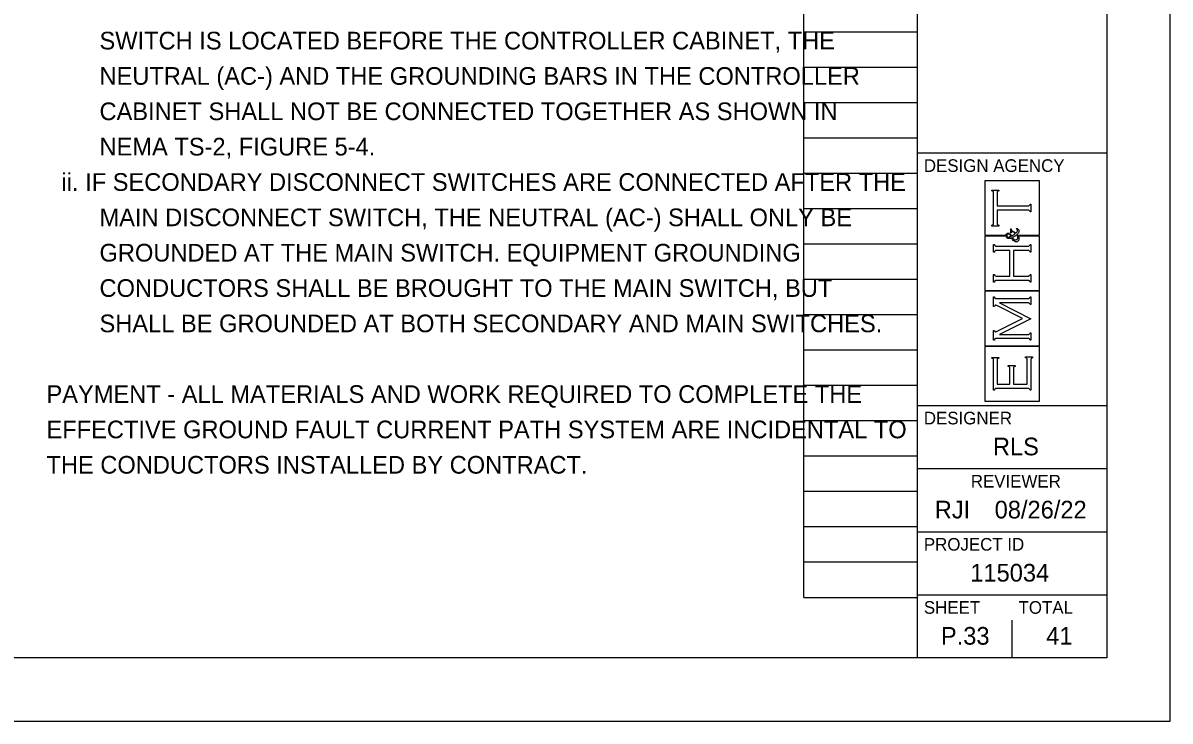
# Model space of a CAD drawing. Extents: x 0 to 34, y -30 to 22.
# Drawn here: x 24.91 to 34, y 0 to 5.53 of the extents above; entities that cross this region are included whole.
import ezdxf

# ---------------------------------------------------------------- set-up
doc = ezdxf.new("R2010")
doc.units = 0
for name, color, linetype in [('SH_Border', 7, 'Continuous'), ('SH_Cut_Line', 7, 'Continuous'), ('SH_Data', 7, 'Continuous'), ('SH_Text', 7, 'Continuous')]:
    doc.layers.add(name, color=color, linetype=linetype)

msp = doc.modelspace()

# ---------------------------------------------------------------- linework, layer by layer
at = {"layer": 'SH_Border'}
for p, q in [((32, 0.5), (32, 21.5)), ((32, 4.5), (33.5, 4.5)), ((32, 2.5), (33.5, 2.5)), ((32, 2), (33.5, 2)), ((32, 1.5), (33.5, 1.5)), ((32, 1), (33.5, 1))]:
    msp.add_line(p, q, dxfattribs=at)
msp.add_lwpolyline([(1.5, 21.5), (33.5, 21.5), (33.5, 0.5), (1.5, 0.5)], close=True, dxfattribs=at)
at = {"layer": 'SH_Cut_Line'}
msp.add_lwpolyline([(0, 0), (34, 0), (34, 22), (0, 22)], close=True, dxfattribs=at)
at = {"layer": 'SH_Data'}
for p, q in [((31.1, 0.98), (31.1, 21.14)), ((32, 0.98), (32, 21.14)), ((31.1, 5.46), (32, 5.46)), ((31.1, 5.18), (32, 5.18)), ((31.1, 4.9), (32, 4.9)), ((31.1, 4.62), (32, 4.62)), ((31.1, 4.34), (32, 4.34)), ((32.966, 4.2797), (32.5341, 4.2797)), ((32.5341, 4.2797), (32.5341, 3.848)), ((32.966, 3.848), (32.966, 4.2797)), ((32.5883, 4.1994), (32.5883, 4.2063)), ((32.5883, 4.2063), (32.6445, 4.2063)), ((32.5938, 4.1981), (32.5883, 4.1994)), ((32.5975, 4.1962), (32.5938, 4.1981)), ((32.5994, 4.1936), (32.5975, 4.1962)), ((32.6012, 4.1911), (32.5994, 4.1936)), ((32.6021, 4.1868), (32.6012, 4.1911)), ((32.6021, 4.1808), (32.6021, 4.1868)), ((32.6021, 3.9469), (32.6021, 4.1808)), ((32.6316, 4.1911), (32.6306, 4.1868)), ((32.6306, 4.1868), (32.6306, 4.1808)), ((32.6306, 4.1808), (32.6306, 4.0808)), ((32.6334, 4.1936), (32.6316, 4.1911)), ((32.6352, 4.1962), (32.6334, 4.1936)), ((32.6389, 4.1981), (32.6352, 4.1962)), ((32.6445, 4.1994), (32.6389, 4.1981)), ((32.6445, 4.2063), (32.6445, 4.1994)), ((32.8875, 4.0855), (32.8895, 4.0892)), ((32.8895, 4.0892), (32.8909, 4.0946)), ((32.8909, 4.0946), (32.8978, 4.0946)), ((32.8978, 4.0946), (32.8978, 4.033)), ((31.1, 4.06), (32, 4.06)), ((32.6306, 4.0808), (32.8723, 4.0808)), ((32.8723, 4.0469), (32.6306, 4.0469)), ((32.6306, 4.0469), (32.6306, 3.9469)), ((32.8723, 4.0808), (32.8782, 4.0808)), ((32.8784, 4.0469), (32.8723, 4.0469)), ((32.8782, 4.0808), (32.8824, 4.0817)), ((32.8826, 4.046), (32.8784, 4.0469)), ((32.8824, 4.0817), (32.885, 4.0836)), ((32.8851, 4.0441), (32.8826, 4.046)), ((32.885, 4.0836), (32.8875, 4.0855)), ((32.8875, 4.0422), (32.8851, 4.0441)), ((32.8895, 4.0385), (32.8875, 4.0422)), ((32.8909, 4.033), (32.8895, 4.0385)), ((32.8978, 4.033), (32.8909, 4.033)), ((32.5883, 3.9283), (32.5938, 3.9296)), ((32.5883, 3.9214), (32.5883, 3.9283)), ((32.6445, 3.9214), (32.5883, 3.9214)), ((32.5938, 3.9296), (32.5975, 3.9315)), ((32.5975, 3.9315), (32.5994, 3.934)), ((32.5994, 3.934), (32.6012, 3.9366)), ((32.6012, 3.9366), (32.6021, 3.9409)), ((32.6021, 3.9409), (32.6021, 3.9469)), ((32.6306, 3.9469), (32.6306, 3.9409)), ((32.6306, 3.9409), (32.6315, 3.9366)), ((32.6315, 3.9366), (32.6334, 3.934)), ((32.6334, 3.934), (32.6352, 3.9315)), ((32.6352, 3.9315), (32.6389, 3.9296)), ((32.6389, 3.9296), (32.6445, 3.9283)), ((32.6445, 3.9283), (32.6445, 3.9214)), ((32.5341, 3.848), (32.6932, 3.848)), ((32.6927, 3.8421), (32.5341, 3.8421)), ((32.5341, 3.8421), (32.5341, 3.4103)), ((32.6932, 3.848), (32.6927, 3.8421)), ((32.7011, 3.8522), (32.7028, 3.8569)), ((32.7011, 3.8465), (32.7011, 3.8522)), ((32.7011, 3.8405), (32.7011, 3.8465)), ((32.7027, 3.8351), (32.7011, 3.8405)), ((32.7061, 3.8304), (32.7027, 3.8351)), ((32.7028, 3.8569), (32.7061, 3.8605)), ((32.7061, 3.8605), (32.7095, 3.8641)), ((32.7104, 3.8243), (32.7061, 3.8304)), ((32.7074, 3.8521), (32.7063, 3.8494)), ((32.7063, 3.8494), (32.7063, 3.8463)), ((32.7063, 3.8463), (32.7063, 3.8421)), ((32.7063, 3.8421), (32.7077, 3.8389)), ((32.7097, 3.8543), (32.7074, 3.8521)), ((32.7077, 3.8389), (32.7106, 3.8368)), ((32.7095, 3.8641), (32.7137, 3.8659)), ((32.7119, 3.8564), (32.7097, 3.8543)), ((32.7167, 3.8213), (32.7104, 3.8243)), ((32.7106, 3.8368), (32.7136, 3.8346)), ((32.7148, 3.8575), (32.7119, 3.8564)), ((32.7136, 3.8346), (32.7164, 3.8336)), ((32.7137, 3.8659), (32.7186, 3.8659)), ((32.7183, 3.8575), (32.7148, 3.8575)), ((32.7164, 3.8336), (32.7192, 3.8336)), ((32.725, 3.8213), (32.7167, 3.8213)), ((32.7227, 3.8575), (32.7183, 3.8575)), ((32.7186, 3.8659), (32.7237, 3.8659)), ((32.7192, 3.8336), (32.7216, 3.8336)), ((32.7216, 3.8336), (32.7243, 3.834)), ((32.7268, 3.856), (32.7227, 3.8575)), ((32.7237, 3.8659), (32.7282, 3.8642)), ((32.7243, 3.834), (32.7272, 3.8348)), ((32.7279, 3.8213), (32.725, 3.8213)), ((32.7304, 3.853), (32.7268, 3.856)), ((32.7272, 3.8348), (32.7301, 3.8356)), ((32.731, 3.8217), (32.7279, 3.8213)), ((32.7282, 3.8642), (32.732, 3.8606)), ((32.7301, 3.8356), (32.7344, 3.8371)), ((32.734, 3.85), (32.7304, 3.853)), ((32.7342, 3.8225), (32.731, 3.8217)), ((32.732, 3.8606), (32.7359, 3.8571)), ((32.7373, 3.8455), (32.734, 3.85)), ((32.7374, 3.8233), (32.7342, 3.8225)), ((32.7344, 3.8371), (32.7401, 3.8394)), ((32.7359, 3.8571), (32.7401, 3.8508)), ((32.7401, 3.8394), (32.7373, 3.8455)), ((32.7415, 3.8248), (32.7374, 3.8233)), ((32.7382, 3.8675), (32.7382, 3.8979)), ((32.7382, 3.8979), (32.7409, 3.8979)), ((32.7409, 3.8675), (32.7382, 3.8675)), ((32.7401, 3.8508), (32.7446, 3.8419)), ((32.7409, 3.8979), (32.7412, 3.8937)), ((32.7411, 3.8694), (32.7409, 3.8675)), ((32.7419, 3.871), (32.7411, 3.8694)), ((32.7412, 3.8937), (32.7422, 3.8906)), ((32.7465, 3.827), (32.7415, 3.8248)), ((32.7432, 3.872), (32.7419, 3.871)), ((32.7422, 3.8906), (32.7437, 3.8886)), ((32.7449, 3.8735), (32.7432, 3.872)), ((32.7437, 3.8886), (32.7452, 3.8866)), ((32.7446, 3.8419), (32.7555, 3.8482)), ((32.7469, 3.8742), (32.7449, 3.8735)), ((32.7452, 3.8866), (32.7497, 3.8834)), ((32.7527, 3.8155), (32.7465, 3.827)), ((32.7491, 3.8742), (32.7469, 3.8742)), ((32.756, 3.8742), (32.7491, 3.8742)), ((32.7497, 3.8834), (32.7574, 3.8792)), ((32.7572, 3.8324), (32.7513, 3.8295)), ((32.7513, 3.8295), (32.7546, 3.8237)), ((32.7546, 3.8237), (32.7583, 3.8194)), ((32.7555, 3.8482), (32.7654, 3.8547)), ((32.7645, 3.8699), (32.756, 3.8742)), ((32.7621, 3.8351), (32.7572, 3.8324)), ((32.7574, 3.8792), (32.765, 3.8749)), ((32.7583, 3.8194), (32.7623, 3.8165)), ((32.7661, 3.8376), (32.7621, 3.8351)), ((32.7623, 3.8165), (32.7663, 3.8136)), ((32.7745, 3.8613), (32.7645, 3.8699)), ((32.765, 3.8749), (32.7721, 3.8701)), ((32.7654, 3.8547), (32.7745, 3.8613)), ((32.7701, 3.8401), (32.7661, 3.8376)), ((32.7764, 3.8445), (32.7701, 3.8401)), ((32.7721, 3.8701), (32.7787, 3.8647)), ((32.785, 3.8509), (32.7764, 3.8445)), ((32.7787, 3.8647), (32.7837, 3.869)), ((32.7814, 3.8996), (32.7834, 3.9023)), ((32.7849, 3.8987), (32.7814, 3.8996)), ((32.7834, 3.9023), (32.7902, 3.9005)), ((32.7837, 3.869), (32.7872, 3.8728)), ((32.7876, 3.897), (32.7849, 3.8987)), ((32.7891, 3.846), (32.785, 3.8509)), ((32.785, 3.8139), (32.7889, 3.8172)), ((32.7872, 3.8728), (32.7891, 3.8762)), ((32.7894, 3.8947), (32.7876, 3.897)), ((32.7889, 3.8172), (32.7929, 3.8205)), ((32.7891, 3.8762), (32.7911, 3.8795)), ((32.7917, 3.8422), (32.7891, 3.846)), ((32.7944, 3.8595), (32.7892, 3.8547)), ((32.7892, 3.8547), (32.7946, 3.8487)), ((32.7912, 3.8924), (32.7894, 3.8947)), ((32.7902, 3.9005), (32.7952, 3.8977)), ((32.7911, 3.8795), (32.7921, 3.8829)), ((32.7921, 3.8896), (32.7912, 3.8924)), ((32.793, 3.8394), (32.7917, 3.8422)), ((32.7921, 3.8863), (32.7921, 3.8896)), ((32.7921, 3.8829), (32.7921, 3.8863)), ((32.7929, 3.8205), (32.7948, 3.825)), ((32.7942, 3.8366), (32.793, 3.8394)), ((32.7948, 3.8337), (32.7942, 3.8366)), ((32.798, 3.8639), (32.7944, 3.8595)), ((32.7946, 3.8487), (32.7983, 3.8433)), ((32.7948, 3.8306), (32.7948, 3.8337)), ((32.7948, 3.825), (32.7948, 3.8306)), ((32.7952, 3.8977), (32.7985, 3.8937)), ((32.8002, 3.868), (32.798, 3.8639)), ((32.7983, 3.8433), (32.8004, 3.8385)), ((32.7985, 3.8937), (32.8018, 3.8898)), ((32.8024, 3.872), (32.8002, 3.868)), ((32.8004, 3.8385), (32.8024, 3.8337)), ((32.8018, 3.8898), (32.8035, 3.8852)), ((32.8035, 3.876), (32.8024, 3.872)), ((32.8024, 3.8337), (32.8035, 3.8286)), ((32.8072, 3.8421), (32.803, 3.848)), ((32.803, 3.848), (32.966, 3.848)), ((32.8035, 3.8852), (32.8035, 3.88)), ((32.8035, 3.88), (32.8035, 3.876)), ((32.8035, 3.8286), (32.8035, 3.8232)), ((32.8035, 3.8232), (32.8035, 3.8152)), ((32.966, 3.8421), (32.8072, 3.8421)), ((32.966, 3.4103), (32.966, 3.8421)), ((31.1, 3.78), (32, 3.78)), ((32.6021, 3.714), (32.6021, 3.7756)), ((32.6021, 3.7756), (32.6091, 3.7756)), ((32.6091, 3.7756), (32.6105, 3.7702)), ((32.6105, 3.7702), (32.6125, 3.7665)), ((32.6148, 3.7251), (32.6123, 3.7232)), ((32.6125, 3.7665), (32.6149, 3.7646)), ((32.6173, 3.7269), (32.6148, 3.7251)), ((32.6149, 3.7646), (32.6174, 3.7627)), ((32.6216, 3.7279), (32.6173, 3.7269)), ((32.6174, 3.7627), (32.6216, 3.7618)), ((32.6216, 3.7618), (32.6277, 3.7618)), ((32.6277, 3.7279), (32.6216, 3.7279)), ((32.6277, 3.7618), (32.8723, 3.7618)), ((32.7315, 3.7279), (32.6277, 3.7279)), ((32.7315, 3.5246), (32.7315, 3.7279)), ((32.7587, 3.8076), (32.7527, 3.8155)), ((32.7645, 3.8035), (32.7587, 3.8076)), ((32.8723, 3.7279), (32.76, 3.7279)), ((32.76, 3.7279), (32.76, 3.5246)), ((32.7703, 3.7993), (32.7645, 3.8035)), ((32.7663, 3.8136), (32.7707, 3.8122)), ((32.7761, 3.7972), (32.7703, 3.7993)), ((32.7707, 3.8122), (32.7753, 3.8122)), ((32.7753, 3.8122), (32.7805, 3.8122)), ((32.7819, 3.7972), (32.7761, 3.7972)), ((32.7805, 3.8122), (32.785, 3.8139)), ((32.7878, 3.7972), (32.7819, 3.7972)), ((32.7929, 3.7995), (32.7878, 3.7972)), ((32.7971, 3.8042), (32.7929, 3.7995)), ((32.8014, 3.8089), (32.7971, 3.8042)), ((32.8035, 3.8152), (32.8014, 3.8089)), ((32.8723, 3.7618), (32.8782, 3.7618)), ((32.8784, 3.7279), (32.8723, 3.7279)), ((32.8782, 3.7618), (32.8824, 3.7627)), ((32.8826, 3.7269), (32.8784, 3.7279)), ((32.8824, 3.7627), (32.8849, 3.7646)), ((32.8851, 3.7251), (32.8826, 3.7269)), ((32.8849, 3.7646), (32.8875, 3.7665)), ((32.8875, 3.7232), (32.8851, 3.7251)), ((32.8875, 3.7665), (32.8895, 3.7701)), ((32.8895, 3.7701), (32.8909, 3.7756)), ((32.8909, 3.7756), (32.8978, 3.7756)), ((32.8978, 3.7756), (32.8978, 3.714)), ((32.6091, 3.714), (32.6021, 3.714)), ((32.6104, 3.7195), (32.6091, 3.714)), ((32.6123, 3.7232), (32.6104, 3.7195)), ((32.8895, 3.7195), (32.8875, 3.7232)), ((32.8909, 3.714), (32.8895, 3.7195)), ((32.8978, 3.714), (32.8909, 3.714)), ((31.1, 3.5), (32, 3.5)), ((32.6021, 3.4768), (32.6021, 3.5385)), ((32.6021, 3.5385), (32.6091, 3.5385)), ((32.6091, 3.4768), (32.6021, 3.4768)), ((32.6091, 3.5385), (32.6105, 3.533)), ((32.6104, 3.4823), (32.6091, 3.4768)), ((32.6123, 3.486), (32.6104, 3.4823)), ((32.6105, 3.533), (32.6125, 3.5293)), ((32.6148, 3.4879), (32.6123, 3.486)), ((32.6125, 3.5293), (32.6149, 3.5274)), ((32.6173, 3.4898), (32.6148, 3.4879)), ((32.6149, 3.5274), (32.6174, 3.5255)), ((32.6216, 3.4907), (32.6173, 3.4898)), ((32.6174, 3.5255), (32.6216, 3.5246)), ((32.6216, 3.5246), (32.6277, 3.5246)), ((32.6277, 3.4907), (32.6216, 3.4907)), ((32.6277, 3.5246), (32.7315, 3.5246)), ((32.8723, 3.4907), (32.6277, 3.4907)), ((32.75, 3.5), (32.75, 3.5)), ((32.76, 3.5246), (32.8723, 3.5246)), ((32.8723, 3.5246), (32.8784, 3.5246)), ((32.8783, 3.4907), (32.8723, 3.4907)), ((32.8826, 3.4898), (32.8783, 3.4907)), ((32.8784, 3.5246), (32.8826, 3.5255)), ((32.8826, 3.5255), (32.8851, 3.5273)), ((32.8851, 3.488), (32.8826, 3.4898)), ((32.8851, 3.5273), (32.8875, 3.5291)), ((32.8875, 3.4862), (32.8851, 3.488)), ((32.8875, 3.5291), (32.8895, 3.5328)), ((32.8895, 3.4825), (32.8875, 3.4862)), ((32.8895, 3.5328), (32.8909, 3.5384)), ((32.8909, 3.4768), (32.8895, 3.4825)), ((32.8909, 3.5384), (32.8978, 3.5384)), ((32.8978, 3.4768), (32.8909, 3.4768)), ((32.8978, 3.5384), (32.8978, 3.4768)), ((32.5341, 3.4103), (32.966, 3.4103)), ((32.9659, 3.4045), (32.5341, 3.4045)), ((32.5341, 3.4045), (32.5341, 2.9727)), ((32.9659, 2.9727), (32.9659, 3.4045)), ((32.6021, 3.2827), (32.6021, 3.36)), ((32.6021, 3.36), (32.6091, 3.36)), ((32.6091, 3.2827), (32.6021, 3.2827)), ((32.6091, 3.36), (32.6105, 3.3545)), ((32.6115, 3.2898), (32.6091, 3.2827)), ((32.6105, 3.3545), (32.6125, 3.3508)), ((32.6146, 3.2933), (32.6115, 3.2898)), ((32.6125, 3.3508), (32.6149, 3.3489)), ((32.6184, 3.2933), (32.6146, 3.2933)), ((32.6149, 3.3489), (32.6174, 3.3471)), ((32.6174, 3.3471), (32.6216, 3.3461)), ((32.6213, 3.2933), (32.6184, 3.2933)), ((32.6262, 3.2916), (32.6213, 3.2933)), ((32.6216, 3.3461), (32.6277, 3.3461)), ((32.6331, 3.2881), (32.6262, 3.2916)), ((32.6277, 3.3461), (32.8723, 3.3461)), ((32.831, 3.189), (32.6331, 3.2881)), ((32.8722, 3.3122), (32.6485, 3.3122)), ((32.6485, 3.3122), (32.8978, 3.1863)), ((32.8783, 3.3122), (32.8722, 3.3122)), ((32.8723, 3.3461), (32.8782, 3.3461)), ((32.8782, 3.3461), (32.8824, 3.347)), ((32.8826, 3.3113), (32.8783, 3.3122)), ((32.8824, 3.347), (32.8849, 3.3489)), ((32.885, 3.3095), (32.8826, 3.3113)), ((32.8849, 3.3489), (32.8875, 3.3508)), ((32.8875, 3.3077), (32.885, 3.3095)), ((32.8875, 3.3508), (32.8895, 3.3545)), ((32.8895, 3.304), (32.8875, 3.3077)), ((32.8895, 3.3545), (32.8909, 3.36)), ((32.8909, 3.2984), (32.8895, 3.304)), ((32.8909, 3.36), (32.8978, 3.36)), ((32.8978, 3.2984), (32.8909, 3.2984)), ((32.8978, 3.36), (32.8978, 3.2984)), ((31.1, 3.22), (32, 3.22)), ((32.6348, 3.0904), (32.831, 3.189)), ((32.8978, 3.1863), (32.6485, 3.062)), ((32.6021, 3.0173), (32.6021, 3.0939)), ((32.6021, 3.0939), (32.6091, 3.0939)), ((32.6091, 3.0939), (32.6115, 3.0868)), ((32.6255, 3.0856), (32.6348, 3.0904)), ((32.6091, 3.0173), (32.6021, 3.0173)), ((32.6104, 3.0228), (32.6091, 3.0173)), ((32.6123, 3.0265), (32.6104, 3.0228)), ((32.6115, 3.0868), (32.6145, 3.0833)), ((32.6148, 3.0283), (32.6123, 3.0265)), ((32.6145, 3.0833), (32.6182, 3.0833)), ((32.6173, 3.0302), (32.6148, 3.0283)), ((32.6216, 3.0312), (32.6173, 3.0302)), ((32.6182, 3.0833), (32.6199, 3.0833)), ((32.6199, 3.0833), (32.6255, 3.0856)), ((32.6277, 3.0312), (32.6216, 3.0312)), ((32.8723, 3.0312), (32.6277, 3.0312)), ((32.6485, 3.062), (32.8722, 3.062)), ((32.8722, 3.062), (32.8781, 3.062)), ((32.8783, 3.0312), (32.8723, 3.0312)), ((32.8781, 3.062), (32.8824, 3.0629)), ((32.8826, 3.0302), (32.8783, 3.0312)), ((32.8824, 3.0629), (32.8849, 3.0648)), ((32.885, 3.0283), (32.8826, 3.0302)), ((32.8849, 3.0648), (32.8875, 3.0666)), ((32.8875, 3.0265), (32.885, 3.0283)), ((32.8875, 3.0666), (32.8895, 3.0703)), ((32.8895, 3.0228), (32.8875, 3.0265)), ((32.8895, 3.0703), (32.8909, 3.0758)), ((32.8909, 3.0173), (32.8895, 3.0228)), ((32.8909, 3.0758), (32.8978, 3.0758)), ((32.8978, 3.0173), (32.8909, 3.0173)), ((32.8978, 3.0758), (32.8978, 3.0173)), ((31.1, 2.94), (32, 2.94)), ((32.5341, 2.9727), (32.9659, 2.9727)), ((32.9659, 2.9669), (32.5341, 2.9669)), ((32.5341, 2.9669), (32.5341, 2.5351)), ((32.9659, 2.5351), (32.9659, 2.9669)), ((32.5883, 2.8742), (32.5883, 2.8812)), ((32.5883, 2.8812), (32.6445, 2.8812)), ((32.5938, 2.8728), (32.5883, 2.8742)), ((32.5975, 2.8708), (32.5938, 2.8728)), ((32.5994, 2.8684), (32.5975, 2.8708)), ((32.6012, 2.8659), (32.5994, 2.8684)), ((32.6021, 2.8617), (32.6012, 2.8659)), ((32.6021, 2.8556), (32.6021, 2.8617)), ((32.6021, 2.6209), (32.6021, 2.8556)), ((32.6316, 2.866), (32.6306, 2.8616)), ((32.6306, 2.8616), (32.6306, 2.8556)), ((32.6306, 2.8556), (32.6306, 2.6686)), ((32.6335, 2.8685), (32.6316, 2.866)), ((32.6354, 2.871), (32.6335, 2.8685)), ((32.6391, 2.8729), (32.6354, 2.871)), ((32.6445, 2.8742), (32.6391, 2.8729)), ((32.6445, 2.8812), (32.6445, 2.8742)), ((32.7176, 2.8095), (32.7176, 2.8165)), ((32.7176, 2.8165), (32.7739, 2.8165)), ((32.7739, 2.8165), (32.7739, 2.8095)), ((32.8555, 2.8773), (32.8555, 2.8842)), ((32.8555, 2.8842), (32.9117, 2.8842)), ((32.861, 2.876), (32.8555, 2.8773)), ((32.8647, 2.8741), (32.861, 2.876)), ((32.8665, 2.8716), (32.8647, 2.8741)), ((32.8684, 2.869), (32.8665, 2.8716)), ((32.8693, 2.8647), (32.8684, 2.869)), ((32.8693, 2.8586), (32.8693, 2.8647)), ((32.8693, 2.6686), (32.8693, 2.8586)), ((32.8988, 2.8688), (32.8978, 2.8645)), ((32.8978, 2.8645), (32.8978, 2.8585)), ((32.8978, 2.8585), (32.8978, 2.6209)), ((32.9007, 2.8713), (32.8988, 2.8688)), ((32.9025, 2.8739), (32.9007, 2.8713)), ((32.9062, 2.8759), (32.9025, 2.8739)), ((32.9117, 2.8773), (32.9062, 2.8759)), ((32.9117, 2.8842), (32.9117, 2.8773)), ((32.7231, 2.8082), (32.7176, 2.8095)), ((32.7268, 2.8063), (32.7231, 2.8082)), ((32.7287, 2.8038), (32.7268, 2.8063)), ((32.7306, 2.8013), (32.7287, 2.8038)), ((32.7315, 2.797), (32.7306, 2.8013)), ((32.7315, 2.7909), (32.7315, 2.797)), ((32.7315, 2.6686), (32.7315, 2.7909)), ((32.7609, 2.8013), (32.76, 2.797)), ((32.76, 2.797), (32.76, 2.7909)), ((32.76, 2.7909), (32.76, 2.6686)), ((32.7628, 2.8038), (32.7609, 2.8013)), ((32.7647, 2.8063), (32.7628, 2.8038)), ((32.7684, 2.8082), (32.7647, 2.8063)), ((32.7739, 2.8095), (32.7684, 2.8082)), ((31.1, 2.66), (32, 2.66)), ((32.6306, 2.6686), (32.7315, 2.6686)), ((32.76, 2.6686), (32.8693, 2.6686)), ((32.6091, 2.6209), (32.6021, 2.6209)), ((32.6105, 2.6264), (32.6091, 2.6209)), ((32.6125, 2.63), (32.6105, 2.6264)), ((32.6149, 2.6319), (32.6125, 2.63)), ((32.6174, 2.6338), (32.6149, 2.6319)), ((32.6216, 2.6347), (32.6174, 2.6338)), ((32.6277, 2.6347), (32.6216, 2.6347)), ((32.8723, 2.6347), (32.6277, 2.6347)), ((32.8784, 2.6347), (32.8723, 2.6347)), ((32.8826, 2.6338), (32.8784, 2.6347)), ((32.8851, 2.632), (32.8826, 2.6338)), ((32.8875, 2.6302), (32.8851, 2.632)), ((32.8895, 2.6265), (32.8875, 2.6302)), ((32.8909, 2.6209), (32.8895, 2.6265)), ((32.8978, 2.6209), (32.8909, 2.6209)), ((32.5341, 2.5351), (32.9659, 2.5351)), ((31.1, 2.38), (32, 2.38)), ((31.1, 2.1), (32, 2.1)), ((31.1, 1.82), (32, 1.82)), ((31.1, 1.54), (32, 1.54)), ((31.1, 1.26), (32, 1.26)), ((31.1, 0.98), (32, 0.98)), ((32.75, 0.5), (32.75, 0.8)), ((32.375, 0.675), (32.375, 0.675))]:
    msp.add_line(p, q, dxfattribs=at)

# ---------------------------------------------------------------- texts
for s, height, p in [('DESIGN AGENCY', 0.1, (32.05, 4.35)), ('DESIGNER', 0.1, (32.05, 2.35)), ('RLS', 0.14, (32.5971, 2.105)), ('REVIEWER', 0.1, (32.4218, 1.85)), ('RJI', 0.14, (32.1364, 1.605)), ('08/26/22', 0.14, (32.6107, 1.605)), ('PROJECT ID', 0.1, (32.05, 1.35)), ('115034', 0.14, (32.4179, 1.105)), ('SHEET', 0.1, (32.05, 0.85)), ('TOTAL', 0.1, (32.8, 0.85)), ('P.33', 0.14, (32.1851, 0.605)), ('41', 0.14, (33.0192, 0.605))]:
    msp.add_text(s, height=height, dxfattribs=at).set_placement(p)
at = {"layer": 'SH_Text'}
for s, p in [('SWITCH IS LOCATED BEFORE THE CONTROLLER CABINET, THE ', (25.521, 5.32)), ('NEUTRAL (AC-) AND THE GROUNDING BARS IN THE CONTROLLER ', (25.521, 5.04)), ('CABINET SHALL NOT BE CONNECTED TOGETHER AS SHOWN IN ', (25.521, 4.76)), ('NEMA TS-2, FIGURE 5-4.', (25.521, 4.48)), ('ii. IF SECONDARY DISCONNECT SWITCHES ARE CONNECTED AFTER THE ', (25.22, 4.2)), ('MAIN DISCONNECT SWITCH, THE NEUTRAL (AC-) SHALL ONLY BE ', (25.521, 3.92)), ('GROUNDED AT THE MAIN SWITCH. EQUIPMENT GROUNDING ', (25.521, 3.64)), ('CONDUCTORS SHALL BE BROUGHT TO THE MAIN SWITCH, BUT ', (25.521, 3.36)), ('SHALL BE GROUNDED AT BOTH SECONDARY AND MAIN SWITCHES.', (25.521, 3.08)), ('PAYMENT - ALL MATERIALS AND WORK REQUIRED TO COMPLETE THE ', (25.101, 2.52)), ('EFFECTIVE GROUND FAULT CURRENT PATH SYSTEM ARE INCIDENTAL TO ', (25.101, 2.24)), ('THE CONDUCTORS INSTALLED BY CONTRACT.', (25.101, 1.96))]:
    msp.add_text(s, height=0.14, dxfattribs=at).set_placement(p)

doc.saveas('drawing.dxf')
